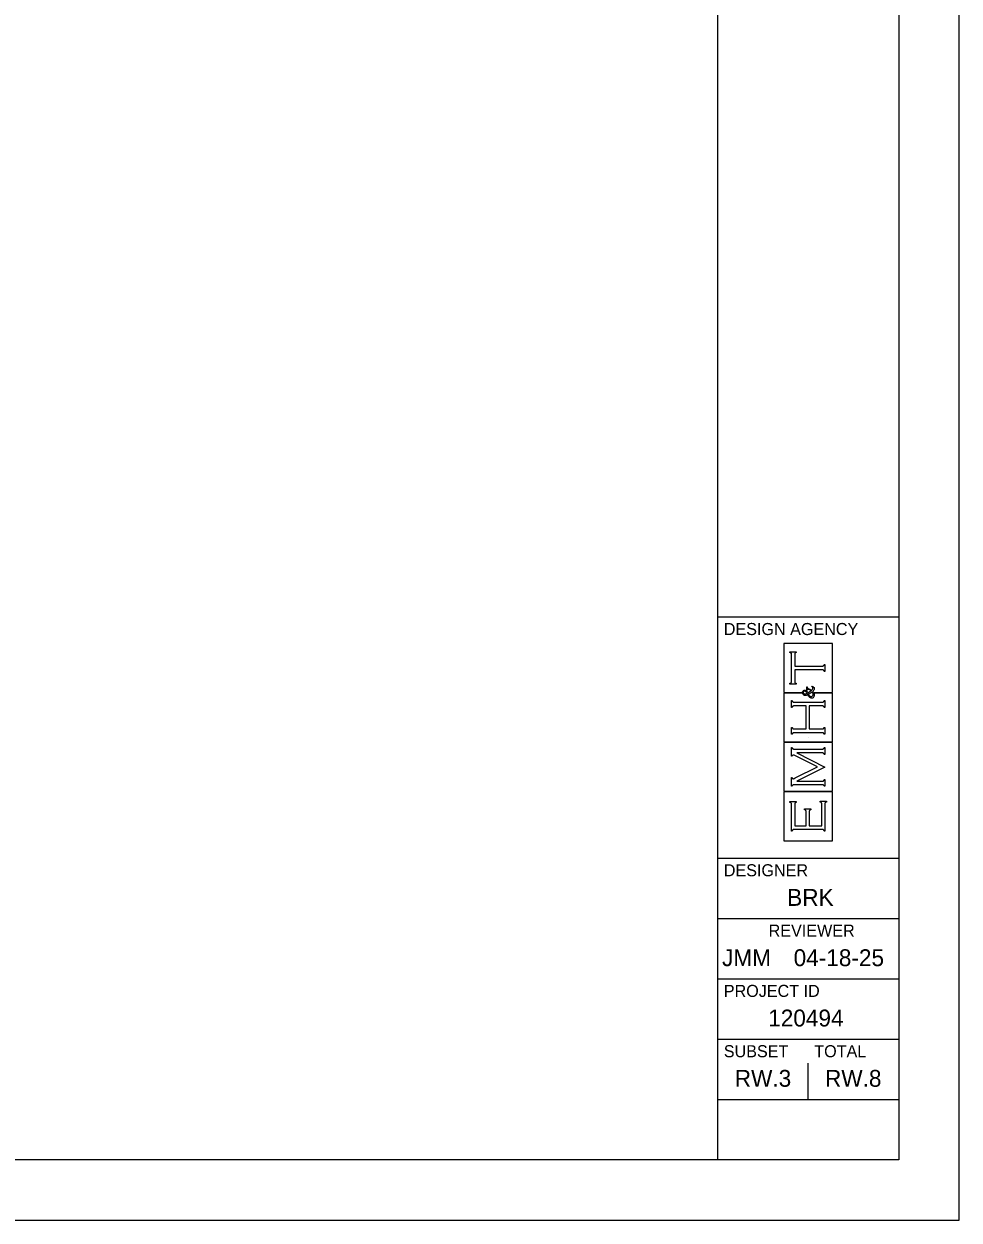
# Model space of a CAD drawing. Extents: x 0 to 34, y 0 to 22.
# Drawn here: x 26.25 to 34, y 0 to 9.92 of the extents above; entities that cross this region are included whole.
import ezdxf

# ---------------------------------------------------------------- set-up
doc = ezdxf.new("R2010")
doc.units = 0
for name, color, linetype in [('RW_P_Esmt_CH', 7, 'Continuous'), ('RW_P_Esmt_TMP', 7, 'Continuous'), ('SC_Scratch1', 7, 'Continuous')]:
    doc.layers.add(name, color=color, linetype=linetype)

msp = doc.modelspace()

# ---------------------------------------------------------------- linework, layer by layer
at = {"layer": 'RW_P_Esmt_CH'}
for p, q in [((32, 0.5), (32, 21.5)), ((32, 5), (33.5, 5)), ((32, 3), (33.5, 3)), ((32, 2.5), (33.5, 2.5)), ((32, 2), (33.5, 2)), ((32, 1.5), (33.5, 1.5)), ((32, 1), (33.5, 1))]:
    msp.add_line(p, q, dxfattribs=at)
msp.add_lwpolyline([(1.5, 21.5), (33.5, 21.5), (33.5, 0.5), (1.5, 0.5)], close=True, dxfattribs=at)
at = {"layer": 'RW_P_Esmt_TMP'}
msp.add_lwpolyline([(0, 0), (34, 0), (34, 22), (0, 22)], close=True, dxfattribs=at)
at = {"layer": 'SC_Scratch1'}
for p, q in [((32.9517, 4.7794), (32.547, 4.7794)), ((32.547, 4.7794), (32.547, 4.3748)), ((32.9517, 4.3748), (32.9517, 4.7794)), ((32.5978, 4.7041), (32.5978, 4.7106)), ((32.5978, 4.7106), (32.6505, 4.7106)), ((32.603, 4.7029), (32.5978, 4.7041)), ((32.6064, 4.7011), (32.603, 4.7029)), ((32.6082, 4.6987), (32.6064, 4.7011)), ((32.6099, 4.6964), (32.6082, 4.6987)), ((32.6108, 4.6924), (32.6099, 4.6964)), ((32.6108, 4.6867), (32.6108, 4.6924)), ((32.6108, 4.4675), (32.6108, 4.6867)), ((32.6383, 4.6964), (32.6375, 4.6924)), ((32.6375, 4.6924), (32.6375, 4.6867)), ((32.6375, 4.6867), (32.6375, 4.593)), ((32.64, 4.6987), (32.6383, 4.6964)), ((32.6418, 4.7011), (32.64, 4.6987)), ((32.6452, 4.7029), (32.6418, 4.7011)), ((32.6505, 4.7041), (32.6452, 4.7029)), ((32.6505, 4.7106), (32.6505, 4.7041)), ((32.6375, 4.593), (32.8639, 4.593)), ((32.8639, 4.593), (32.8695, 4.593)), ((32.8695, 4.593), (32.8734, 4.5939)), ((32.8734, 4.5939), (32.8758, 4.5956)), ((32.8758, 4.5956), (32.8782, 4.5974)), ((32.8782, 4.5974), (32.88, 4.6008)), ((32.88, 4.6008), (32.8814, 4.606)), ((32.8814, 4.606), (32.8879, 4.606)), ((32.8879, 4.606), (32.8879, 4.5483)), ((32.6108, 4.4619), (32.6108, 4.4675)), ((32.8639, 4.5612), (32.6375, 4.5612)), ((32.6375, 4.5612), (32.6375, 4.4676)), ((32.6375, 4.4676), (32.6375, 4.4619)), ((32.8696, 4.5612), (32.8639, 4.5612)), ((32.8736, 4.5604), (32.8696, 4.5612)), ((32.8759, 4.5586), (32.8736, 4.5604)), ((32.8782, 4.5568), (32.8759, 4.5586)), ((32.88, 4.5534), (32.8782, 4.5568)), ((32.8814, 4.5483), (32.88, 4.5534)), ((32.8879, 4.5483), (32.8814, 4.5483)), ((32.547, 4.3748), (32.6961, 4.3748)), ((32.6956, 4.3694), (32.5471, 4.3694)), ((32.5471, 4.3694), (32.5471, 3.9648)), ((32.5978, 4.4501), (32.603, 4.4513)), ((32.5978, 4.4436), (32.5978, 4.4501)), ((32.6505, 4.4436), (32.5978, 4.4436)), ((32.603, 4.4513), (32.6064, 4.4531)), ((32.6064, 4.4531), (32.6082, 4.4555)), ((32.6082, 4.4555), (32.6099, 4.4579)), ((32.6099, 4.4579), (32.6108, 4.4619)), ((32.6375, 4.4619), (32.6383, 4.4579)), ((32.6383, 4.4579), (32.6401, 4.4555)), ((32.6401, 4.4555), (32.6418, 4.4531)), ((32.6418, 4.4531), (32.6452, 4.4513)), ((32.6452, 4.4513), (32.6505, 4.4501)), ((32.6505, 4.4501), (32.6505, 4.4436)), ((32.6961, 4.3748), (32.6956, 4.3694)), ((32.7035, 4.3788), (32.7051, 4.3832)), ((32.7035, 4.3734), (32.7035, 4.3788)), ((32.7035, 4.3678), (32.7035, 4.3734)), ((32.705, 4.3628), (32.7035, 4.3678)), ((32.7051, 4.3832), (32.7082, 4.3866)), ((32.7082, 4.3866), (32.7114, 4.39)), ((32.7094, 4.3787), (32.7083, 4.3762)), ((32.7083, 4.3762), (32.7083, 4.3732)), ((32.7083, 4.3732), (32.7083, 4.3693)), ((32.7083, 4.3693), (32.7097, 4.3664)), ((32.7115, 4.3807), (32.7094, 4.3787)), ((32.7097, 4.3664), (32.7125, 4.3644)), ((32.7114, 4.39), (32.7153, 4.3917)), ((32.7137, 4.3827), (32.7115, 4.3807)), ((32.7125, 4.3644), (32.7152, 4.3623)), ((32.7164, 4.3837), (32.7137, 4.3827)), ((32.7153, 4.3917), (32.7199, 4.3917)), ((32.7196, 4.3837), (32.7164, 4.3837)), ((32.7238, 4.3837), (32.7196, 4.3837)), ((32.7199, 4.3917), (32.7247, 4.3917)), ((32.7276, 4.3823), (32.7238, 4.3837)), ((32.7247, 4.3917), (32.7289, 4.39)), ((32.731, 4.3795), (32.7276, 4.3823)), ((32.7279, 4.3625), (32.7307, 4.3632)), ((32.7289, 4.39), (32.7325, 4.3867)), ((32.7307, 4.3632), (32.7347, 4.3647)), ((32.7344, 4.3767), (32.731, 4.3795)), ((32.7325, 4.3867), (32.7361, 4.3834)), ((32.7374, 4.3725), (32.7344, 4.3767)), ((32.7347, 4.3647), (32.7401, 4.3668)), ((32.7361, 4.3834), (32.74, 4.3775)), ((32.7401, 4.3668), (32.7374, 4.3725)), ((32.7383, 4.3931), (32.7383, 4.4216)), ((32.7383, 4.4216), (32.7408, 4.4216)), ((32.7408, 4.3931), (32.7383, 4.3931)), ((32.74, 4.3775), (32.7443, 4.3691)), ((32.7408, 4.4216), (32.7411, 4.4177)), ((32.741, 4.395), (32.7408, 4.3931)), ((32.7418, 4.3964), (32.741, 4.395)), ((32.7411, 4.4177), (32.742, 4.4148)), ((32.743, 4.3974), (32.7418, 4.3964)), ((32.742, 4.4148), (32.7434, 4.4129)), ((32.7446, 4.3987), (32.743, 4.3974)), ((32.7434, 4.4129), (32.7448, 4.411)), ((32.7443, 4.3691), (32.7545, 4.3751)), ((32.7464, 4.3994), (32.7446, 4.3987)), ((32.7448, 4.411), (32.7491, 4.4081)), ((32.7485, 4.3994), (32.7464, 4.3994)), ((32.7549, 4.3994), (32.7485, 4.3994)), ((32.7491, 4.4081), (32.7562, 4.4041)), ((32.7545, 4.3751), (32.7638, 4.3812)), ((32.7629, 4.3954), (32.7549, 4.3994)), ((32.7562, 4.4041), (32.7634, 4.4001)), ((32.7644, 4.3651), (32.7607, 4.3628)), ((32.7723, 4.3874), (32.7629, 4.3954)), ((32.7634, 4.4001), (32.77, 4.3956)), ((32.7638, 4.3812), (32.7723, 4.3874)), ((32.7681, 4.3674), (32.7644, 4.3651)), ((32.7741, 4.3716), (32.7681, 4.3674)), ((32.77, 4.3956), (32.7762, 4.3905)), ((32.7821, 4.3776), (32.7741, 4.3716)), ((32.7762, 4.3905), (32.7809, 4.3945)), ((32.7788, 4.4232), (32.7806, 4.4258)), ((32.7821, 4.4224), (32.7788, 4.4232)), ((32.7806, 4.4258), (32.787, 4.4241)), ((32.7809, 4.3945), (32.7841, 4.3981)), ((32.7846, 4.4208), (32.7821, 4.4224)), ((32.7859, 4.373), (32.7821, 4.3776)), ((32.7841, 4.3981), (32.786, 4.4013)), ((32.7863, 4.4187), (32.7846, 4.4208)), ((32.7884, 4.3694), (32.7859, 4.373)), ((32.786, 4.4013), (32.7879, 4.4044)), ((32.7909, 4.3856), (32.786, 4.3811)), ((32.786, 4.3811), (32.7911, 4.3755)), ((32.7879, 4.4165), (32.7863, 4.4187)), ((32.787, 4.4241), (32.7917, 4.4214)), ((32.7888, 4.4139), (32.7879, 4.4165)), ((32.7879, 4.4044), (32.7888, 4.4076)), ((32.7896, 4.3668), (32.7884, 4.3694)), ((32.7888, 4.4108), (32.7888, 4.4139)), ((32.7888, 4.4076), (32.7888, 4.4108)), ((32.7907, 4.3642), (32.7896, 4.3668)), ((32.7913, 4.3614), (32.7907, 4.3642)), ((32.7943, 4.3898), (32.7909, 4.3856)), ((32.7911, 4.3755), (32.7946, 4.3705)), ((32.7917, 4.4214), (32.7948, 4.4177)), ((32.7964, 4.3936), (32.7943, 4.3898)), ((32.7946, 4.3705), (32.7965, 4.366)), ((32.7948, 4.4177), (32.7979, 4.414)), ((32.7984, 4.3974), (32.7964, 4.3936)), ((32.7965, 4.366), (32.7985, 4.3615)), ((32.7979, 4.414), (32.7994, 4.4097)), ((32.7994, 4.4011), (32.7984, 4.3974)), ((32.8029, 4.3694), (32.799, 4.3748)), ((32.799, 4.3748), (32.9517, 4.3748)), ((32.7994, 4.4097), (32.7994, 4.4048)), ((32.7994, 4.4048), (32.7994, 4.4011)), ((32.9517, 4.3694), (32.8029, 4.3694)), ((32.9517, 3.9648), (32.9517, 4.3694)), ((32.6108, 4.2493), (32.6108, 4.3071)), ((32.6108, 4.3071), (32.6173, 4.3071)), ((32.6173, 4.3071), (32.6186, 4.3019)), ((32.6186, 4.3019), (32.6205, 4.2985)), ((32.6205, 4.2985), (32.6228, 4.2967)), ((32.6228, 4.2967), (32.6251, 4.2949)), ((32.6251, 4.2949), (32.629, 4.2941)), ((32.629, 4.2941), (32.6347, 4.2941)), ((32.6347, 4.2941), (32.8639, 4.2941)), ((32.7082, 4.3583), (32.705, 4.3628)), ((32.7123, 4.3526), (32.7082, 4.3583)), ((32.7182, 4.3498), (32.7123, 4.3526)), ((32.7152, 4.3623), (32.7179, 4.3614)), ((32.7179, 4.3614), (32.7205, 4.3614)), ((32.7259, 4.3498), (32.7182, 4.3498)), ((32.7205, 4.3614), (32.7227, 4.3614)), ((32.7227, 4.3614), (32.7252, 4.3617)), ((32.7252, 4.3617), (32.7279, 4.3625)), ((32.7286, 4.3498), (32.7259, 4.3498)), ((32.7315, 4.3502), (32.7286, 4.3498)), ((32.7345, 4.3509), (32.7315, 4.3502)), ((32.7375, 4.3517), (32.7345, 4.3509)), ((32.7413, 4.3531), (32.7375, 4.3517)), ((32.746, 4.3552), (32.7413, 4.3531)), ((32.7519, 4.3444), (32.746, 4.3552)), ((32.7561, 4.3603), (32.7505, 4.3575)), ((32.7505, 4.3575), (32.7537, 4.3521)), ((32.7575, 4.337), (32.7519, 4.3444)), ((32.7537, 4.3521), (32.7571, 4.3481)), ((32.7607, 4.3628), (32.7561, 4.3603)), ((32.7571, 4.3481), (32.7609, 4.3454)), ((32.7629, 4.3331), (32.7575, 4.337)), ((32.7609, 4.3454), (32.7646, 4.3427)), ((32.7684, 4.3292), (32.7629, 4.3331)), ((32.7646, 4.3427), (32.7687, 4.3413)), ((32.7738, 4.3273), (32.7684, 4.3292)), ((32.7687, 4.3413), (32.7731, 4.3413)), ((32.7731, 4.3413), (32.7779, 4.3413)), ((32.7793, 4.3273), (32.7738, 4.3273)), ((32.7779, 4.3413), (32.7822, 4.3429)), ((32.7848, 4.3273), (32.7793, 4.3273)), ((32.7822, 4.3429), (32.7858, 4.346)), ((32.7895, 4.3294), (32.7848, 4.3273)), ((32.7858, 4.346), (32.7895, 4.3491)), ((32.7895, 4.3491), (32.7913, 4.3533)), ((32.7935, 4.3338), (32.7895, 4.3294)), ((32.7913, 4.3586), (32.7913, 4.3614)), ((32.7913, 4.3533), (32.7913, 4.3586)), ((32.7975, 4.3382), (32.7935, 4.3338)), ((32.7994, 4.3441), (32.7975, 4.3382)), ((32.7985, 4.3615), (32.7994, 4.3567)), ((32.7994, 4.3567), (32.7994, 4.3516)), ((32.7994, 4.3516), (32.7994, 4.3441)), ((32.8639, 4.2941), (32.8695, 4.2941)), ((32.8695, 4.2941), (32.8734, 4.2949)), ((32.8734, 4.2949), (32.8758, 4.2967)), ((32.8758, 4.2967), (32.8782, 4.2985)), ((32.8782, 4.2985), (32.88, 4.3019)), ((32.88, 4.3019), (32.8814, 4.3071)), ((32.8814, 4.3071), (32.8879, 4.3071)), ((32.8879, 4.3071), (32.8879, 4.2493)), ((32.6173, 4.2493), (32.6108, 4.2493)), ((32.6185, 4.2545), (32.6173, 4.2493)), ((32.6203, 4.2579), (32.6185, 4.2545)), ((32.6227, 4.2597), (32.6203, 4.2579)), ((32.625, 4.2614), (32.6227, 4.2597)), ((32.629, 4.2623), (32.625, 4.2614)), ((32.6347, 4.2623), (32.629, 4.2623)), ((32.732, 4.2623), (32.6347, 4.2623)), ((32.732, 4.0718), (32.732, 4.2623)), ((32.8639, 4.2623), (32.7587, 4.2623)), ((32.7587, 4.2623), (32.7587, 4.0718)), ((32.8696, 4.2623), (32.8639, 4.2623)), ((32.8736, 4.2614), (32.8696, 4.2623)), ((32.8759, 4.2597), (32.8736, 4.2614)), ((32.8782, 4.2579), (32.8759, 4.2597)), ((32.88, 4.2545), (32.8782, 4.2579)), ((32.8814, 4.2493), (32.88, 4.2545)), ((32.8879, 4.2493), (32.8814, 4.2493)), ((32.6108, 4.0271), (32.6108, 4.0848)), ((32.6108, 4.0848), (32.6173, 4.0848)), ((32.6173, 4.0848), (32.6186, 4.0797)), ((32.6186, 4.0797), (32.6205, 4.0762)), ((32.6205, 4.0762), (32.6228, 4.0745)), ((32.6228, 4.0745), (32.6251, 4.0727)), ((32.6251, 4.0727), (32.629, 4.0718)), ((32.629, 4.0718), (32.6347, 4.0718)), ((32.6347, 4.0718), (32.732, 4.0718)), ((32.7587, 4.0718), (32.8639, 4.0718)), ((32.8639, 4.0718), (32.8696, 4.0718)), ((32.8696, 4.0718), (32.8736, 4.0727)), ((32.8736, 4.0727), (32.8759, 4.0744)), ((32.8759, 4.0744), (32.8782, 4.076)), ((32.8782, 4.076), (32.88, 4.0795)), ((32.88, 4.0795), (32.8814, 4.0848)), ((32.8814, 4.0848), (32.8879, 4.0848)), ((32.8879, 4.0848), (32.8879, 4.0271)), ((32.6173, 4.0271), (32.6108, 4.0271)), ((32.6185, 4.0322), (32.6173, 4.0271)), ((32.6203, 4.0357), (32.6185, 4.0322)), ((32.6227, 4.0374), (32.6203, 4.0357)), ((32.625, 4.0392), (32.6227, 4.0374)), ((32.6291, 4.0401), (32.625, 4.0392)), ((32.6347, 4.0401), (32.6291, 4.0401)), ((32.8639, 4.0401), (32.6347, 4.0401)), ((32.75, 4), (32.75, 4)), ((32.8696, 4.0401), (32.8639, 4.0401)), ((32.8736, 4.0392), (32.8696, 4.0401)), ((32.8759, 4.0375), (32.8736, 4.0392)), ((32.8782, 4.0358), (32.8759, 4.0375)), ((32.88, 4.0324), (32.8782, 4.0358)), ((32.8814, 4.0271), (32.88, 4.0324)), ((32.8879, 4.0271), (32.8814, 4.0271)), ((32.9516, 3.9593), (32.547, 3.9593)), ((32.547, 3.9593), (32.547, 3.5547)), ((32.5471, 3.9648), (32.9517, 3.9648)), ((32.6108, 3.8452), (32.6108, 3.9176)), ((32.6108, 3.9176), (32.6173, 3.9176)), ((32.6173, 3.9176), (32.6186, 3.9124)), ((32.6186, 3.9124), (32.6205, 3.909)), ((32.6205, 3.909), (32.6228, 3.9072)), ((32.6228, 3.9072), (32.6251, 3.9055)), ((32.6251, 3.9055), (32.6291, 3.9046)), ((32.6291, 3.9046), (32.6347, 3.9046)), ((32.6347, 3.9046), (32.8639, 3.9046)), ((32.8639, 3.8728), (32.6543, 3.8728)), ((32.6543, 3.8728), (32.8879, 3.7548)), ((32.8639, 3.9046), (32.8695, 3.9046)), ((32.8696, 3.8728), (32.8639, 3.8728)), ((32.8695, 3.9046), (32.8734, 3.9055)), ((32.8736, 3.872), (32.8696, 3.8728)), ((32.8734, 3.9055), (32.8758, 3.9072)), ((32.8759, 3.8703), (32.8736, 3.872)), ((32.8758, 3.9072), (32.8782, 3.909)), ((32.8782, 3.8686), (32.8759, 3.8703)), ((32.8782, 3.909), (32.88, 3.9124)), ((32.88, 3.8651), (32.8782, 3.8686)), ((32.88, 3.9124), (32.8814, 3.9176)), ((32.8814, 3.9176), (32.8879, 3.9176)), ((32.8879, 3.9176), (32.8879, 3.8598)), ((32.9517, 3.5547), (32.9516, 3.9593)), ((32.6173, 3.8452), (32.6108, 3.8452)), ((32.6196, 3.8518), (32.6173, 3.8452)), ((32.6225, 3.8551), (32.6196, 3.8518)), ((32.626, 3.8551), (32.6225, 3.8551)), ((32.6287, 3.8551), (32.626, 3.8551)), ((32.6333, 3.8535), (32.6287, 3.8551)), ((32.6398, 3.8502), (32.6333, 3.8535)), ((32.8253, 3.7574), (32.6398, 3.8502)), ((32.8814, 3.8598), (32.88, 3.8651)), ((32.8879, 3.8598), (32.8814, 3.8598)), ((32.6414, 3.665), (32.8253, 3.7574)), ((32.8879, 3.7548), (32.6543, 3.6383)), ((32.6108, 3.5965), (32.6108, 3.6682)), ((32.6108, 3.6682), (32.6173, 3.6682)), ((32.6173, 3.5965), (32.6108, 3.5965)), ((32.6173, 3.6682), (32.6196, 3.6616)), ((32.6185, 3.6016), (32.6173, 3.5965)), ((32.6203, 3.605), (32.6185, 3.6016)), ((32.6196, 3.6616), (32.6224, 3.6583)), ((32.6227, 3.6068), (32.6203, 3.605)), ((32.6224, 3.6583), (32.6258, 3.6583)), ((32.625, 3.6086), (32.6227, 3.6068)), ((32.6291, 3.6094), (32.625, 3.6086)), ((32.6258, 3.6583), (32.6274, 3.6583)), ((32.6274, 3.6583), (32.6326, 3.6605)), ((32.6347, 3.6094), (32.6291, 3.6094)), ((32.6326, 3.6605), (32.6414, 3.665)), ((32.8639, 3.6095), (32.6347, 3.6094)), ((32.6543, 3.6383), (32.8639, 3.6383)), ((32.8639, 3.6383), (32.8694, 3.6383)), ((32.8696, 3.6095), (32.8639, 3.6095)), ((32.8694, 3.6383), (32.8734, 3.6392)), ((32.8736, 3.6086), (32.8696, 3.6095)), ((32.8734, 3.6392), (32.8758, 3.641)), ((32.8759, 3.6068), (32.8736, 3.6086)), ((32.8758, 3.641), (32.8782, 3.6427)), ((32.8782, 3.6051), (32.8759, 3.6068)), ((32.8782, 3.6427), (32.88, 3.6462)), ((32.88, 3.6016), (32.8782, 3.6051)), ((32.88, 3.6462), (32.8814, 3.6513)), ((32.8814, 3.5965), (32.88, 3.6016)), ((32.8814, 3.6513), (32.8879, 3.6513)), ((32.8879, 3.5965), (32.8814, 3.5965)), ((32.8879, 3.6513), (32.8879, 3.5965)), ((32.547, 3.5547), (32.9517, 3.5547)), ((32.9517, 3.5493), (32.547, 3.5492)), ((32.547, 3.5492), (32.547, 3.1447)), ((32.8482, 3.4653), (32.8482, 3.4718)), ((32.8482, 3.4718), (32.9009, 3.4718)), ((32.9009, 3.4718), (32.9009, 3.4653)), ((32.9517, 3.1447), (32.9517, 3.5493)), ((32.5978, 3.4624), (32.5978, 3.4689)), ((32.5978, 3.4689), (32.6505, 3.4689)), ((32.603, 3.4611), (32.5978, 3.4624)), ((32.6065, 3.4592), (32.603, 3.4611)), ((32.6082, 3.4569), (32.6065, 3.4592)), ((32.61, 3.4546), (32.6082, 3.4569)), ((32.6108, 3.4506), (32.61, 3.4546)), ((32.6108, 3.4449), (32.6108, 3.4506)), ((32.6108, 3.225), (32.6108, 3.4449)), ((32.6384, 3.4546), (32.6375, 3.4506)), ((32.6375, 3.4506), (32.6375, 3.4449)), ((32.6375, 3.4449), (32.6375, 3.2697)), ((32.6402, 3.457), (32.6384, 3.4546)), ((32.642, 3.4594), (32.6402, 3.457)), ((32.6454, 3.4612), (32.642, 3.4594)), ((32.6505, 3.4624), (32.6454, 3.4612)), ((32.6505, 3.4689), (32.6505, 3.4624)), ((32.719, 3.4018), (32.719, 3.4083)), ((32.719, 3.4083), (32.7717, 3.4083)), ((32.7242, 3.4006), (32.719, 3.4018)), ((32.7276, 3.3988), (32.7242, 3.4006)), ((32.7294, 3.3964), (32.7276, 3.3988)), ((32.7312, 3.394), (32.7294, 3.3964)), ((32.732, 3.39), (32.7312, 3.394)), ((32.732, 3.3844), (32.732, 3.39)), ((32.732, 3.2697), (32.732, 3.3844)), ((32.7596, 3.394), (32.7587, 3.39)), ((32.7587, 3.39), (32.7587, 3.3844)), ((32.7587, 3.3844), (32.7587, 3.2697)), ((32.7614, 3.3964), (32.7596, 3.394)), ((32.7631, 3.3988), (32.7614, 3.3964)), ((32.7666, 3.4006), (32.7631, 3.3988)), ((32.7717, 3.4018), (32.7666, 3.4006)), ((32.7717, 3.4083), (32.7717, 3.4018)), ((32.8533, 3.4641), (32.8482, 3.4653)), ((32.8568, 3.4623), (32.8533, 3.4641)), ((32.8586, 3.4599), (32.8568, 3.4623)), ((32.8603, 3.4575), (32.8586, 3.4599)), ((32.8612, 3.4535), (32.8603, 3.4575)), ((32.8612, 3.4478), (32.8612, 3.4535)), ((32.8612, 3.2697), (32.8612, 3.4478)), ((32.8888, 3.4573), (32.8879, 3.4533)), ((32.8879, 3.4533), (32.8879, 3.4476)), ((32.8879, 3.4476), (32.8879, 3.225)), ((32.8905, 3.4597), (32.8888, 3.4573)), ((32.8923, 3.4621), (32.8905, 3.4597)), ((32.8957, 3.4639), (32.8923, 3.4621)), ((32.9009, 3.4653), (32.8957, 3.4639)), ((32.6173, 3.225), (32.6108, 3.225)), ((32.6187, 3.2301), (32.6173, 3.225)), ((32.6205, 3.2336), (32.6187, 3.2301)), ((32.6228, 3.2354), (32.6205, 3.2336)), ((32.6251, 3.2371), (32.6228, 3.2354)), ((32.6291, 3.238), (32.6251, 3.2371)), ((32.6348, 3.238), (32.6291, 3.238)), ((32.864, 3.238), (32.6348, 3.238)), ((32.6375, 3.2697), (32.732, 3.2697)), ((32.7587, 3.2697), (32.8612, 3.2697)), ((32.8696, 3.238), (32.864, 3.238)), ((32.8736, 3.2372), (32.8696, 3.238)), ((32.8759, 3.2355), (32.8736, 3.2372)), ((32.8782, 3.2338), (32.8759, 3.2355)), ((32.88, 3.2303), (32.8782, 3.2338)), ((32.8814, 3.225), (32.88, 3.2303)), ((32.8879, 3.225), (32.8814, 3.225)), ((32.547, 3.1447), (32.9517, 3.1447)), ((32.75, 1), (32.75, 1.3))]:
    msp.add_line(p, q, dxfattribs=at)

# ---------------------------------------------------------------- texts
for s, height, p in [('DESIGN AGENCY', 0.1, (32.05, 4.85)), ('DESIGNER', 0.1, (32.05, 2.85)), ('BRK', 0.14, (32.5754, 2.605)), ('REVIEWER', 0.1, (32.4218, 2.35)), ('JMM', 0.14, (32.0355, 2.105)), ('04-18-25', 0.14, (32.6287, 2.105)), ('PROJECT ID', 0.1, (32.05, 1.85)), ('120494', 0.14, (32.4179, 1.605)), ('SUBSET', 0.1, (32.05, 1.35)), ('TOTAL', 0.1, (32.8, 1.35)), ('RW.3', 0.14, (32.1409, 1.105)), ('RW.8', 0.14, (32.8888, 1.105))]:
    msp.add_text(s, height=height, dxfattribs=at).set_placement(p)

doc.saveas('drawing.dxf')
